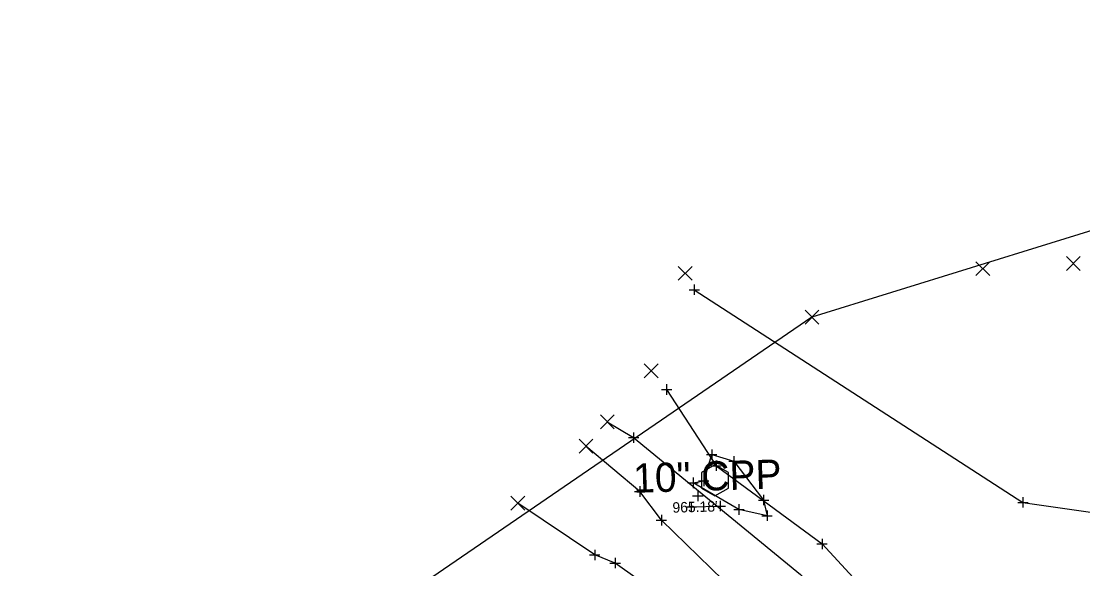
# Model space of a CAD drawing. Extents: x 120332 to 120776, y 463407 to 463745.
# Drawn here: x 120359.6 to 120461.5, y 463602.7 to 463655.3 of the extents above; entities that cross this region are included whole.
import ezdxf

# ---------------------------------------------------------------- set-up
doc = ezdxf.new("R2010")
doc.units = 0
for name, color, linetype in [('DR_X_Erosion_Control', 7, 'Continuous'), ('DR_X_Storm_Sewer', 7, 'Continuous'), ('DR_X_Text', 7, 'Continuous'), ('DV_X_Property_Line', 7, 'Continuous'), ('RD_X_RR_Cells', 7, 'Continuous'), ('SC_Scratch1', 7, 'Continuous'), ('SV_P_Control_Cells_Set', 7, 'Continuous'), ('SV_P_Mon_Cells_Set', 7, 'Continuous'), ('SV_X_Break_Lines', 7, 'Continuous'), ('SV_X_Mon_Cells_Found', 7, 'Continuous'), ('SV_X_Random_Point', 7, 'Continuous'), ('SV_X_Terrain_Boundary', 7, 'Continuous')]:
    doc.layers.add(name, color=color, linetype=linetype)

msp = doc.modelspace()

# ---------------------------------------------------------------- linework, layer by layer
at = {"layer": 'DR_X_Erosion_Control'}
msp.add_lwpolyline([(120425.12, 463611.16), (120425.88, 463613.69), (120428.02, 463613.05), (120430.86, 463609.33), (120431.19, 463607.83), (120428.5, 463608.42), (120424.09, 463610.98)], close=True, dxfattribs=at)
at = {"layer": 'DR_X_Storm_Sewer'}
msp.add_line((120423.92, 463608.67), (120426.71, 463608.75), dxfattribs=at)
at = {"layer": 'DV_X_Property_Line'}
for p, q in [((120423.92, 463609.17), (120423.92, 463608.17)), ((120426.71, 463609.25), (120426.71, 463608.25)), ((120423.42, 463608.67), (120424.42, 463608.67)), ((120423.92, 463608.67), (120423.92, 463608.67)), ((120426.21, 463608.75), (120427.21, 463608.75)), ((120426.71, 463608.75), (120426.71, 463608.75))]:
    msp.add_line(p, q, dxfattribs=at)
at = {"layer": 'RD_X_RR_Cells'}
for points in [[(120421.56, 463619.93), (120426.3, 463612.62), (120436.47, 463605.12), (120443.17, 463597.87), (120449.32, 463591.39), (120456.91, 463583.55), (120459.12, 463582.05), (120462.23, 463580.42), (120466.75, 463584.83), (120476.93, 463591.15), (120482.16, 463596.63), (120497.16, 463604.58), (120521.1, 463620.25), (120539.56, 463634.42)], [(120375.09, 463513.46), (120396.65, 463529.7), (120416.31, 463546.41), (120423.97, 463550.77), (120436.34, 463560.17), (120443.81, 463566.35), (120445.29, 463570.72), (120445.41, 463574.22), (120441.35, 463579.5), (120435.84, 463588.34), (120428.62, 463594.75), (120416.62, 463603.29), (120414.66, 463604.06), (120407.29, 463609.02)]]:
    msp.add_lwpolyline(points, dxfattribs=at)
at = {"layer": 'SC_Scratch1'}
msp.add_lwpolyline([(120424.89, 463610.47), (120426.19, 463609.72), (120427.49, 463610.47), (120427.49, 463611.97), (120426.19, 463612.72), (120424.89, 463611.97), (120424.89, 463610.47)], dxfattribs=at)
at = {"layer": 'SV_P_Control_Cells_Set'}
for p, q in [((120459.91, 463631.36), (120461.25, 463632.69)), ((120459.91, 463632.69), (120461.25, 463631.36)), ((120422.67, 463630.41), (120424, 463631.74)), ((120422.67, 463631.74), (120424, 463630.41)), ((120451.24, 463630.85), (120452.57, 463632.18)), ((120451.24, 463632.18), (120452.57, 463630.85)), ((120434.84, 463626.19), (120436.17, 463627.53)), ((120434.84, 463627.53), (120436.17, 463626.19)), ((120419.41, 463621.06), (120420.74, 463622.39)), ((120419.41, 463622.39), (120420.74, 463621.06)), ((120415.2, 463616.17), (120416.53, 463617.5)), ((120415.2, 463617.5), (120416.53, 463616.17)), ((120413.16, 463613.83), (120414.49, 463615.16)), ((120413.16, 463615.16), (120414.49, 463613.83)), ((120406.62, 463608.36), (120407.96, 463609.69)), ((120406.62, 463609.69), (120407.96, 463608.36))]:
    msp.add_line(p, q, dxfattribs=at)
at = {"layer": 'SV_P_Mon_Cells_Set'}
msp.add_lwpolyline([(120424.21, 463629.5), (120455.74, 463609.1), (120479.05, 463605.78), (120493.61, 463611.68), (120534.99, 463638.96)], dxfattribs=at)
at = {"layer": 'SV_X_Break_Lines'}
msp.add_lwpolyline([(120415.86, 463616.83), (120418.39, 463615.32), (120434.39, 463602.18), (120440.95, 463596.06), (120447.6, 463588.4), (120454.45, 463580.2), (120458.76, 463578.15)], dxfattribs=at)
at = {"layer": 'SV_X_Mon_Cells_Found'}
for p, q in [((120423.71, 463629.5), (120424.71, 463629.5)), ((120424.21, 463630), (120424.21, 463629)), ((120424.21, 463629.5), (120424.21, 463629.5)), ((120421.56, 463620.43), (120421.56, 463619.43)), ((120421.06, 463619.93), (120422.06, 463619.93)), ((120421.56, 463619.93), (120421.56, 463619.93)), ((120417.89, 463615.32), (120418.89, 463615.32)), ((120418.39, 463615.82), (120418.39, 463614.82)), ((120418.39, 463615.32), (120418.39, 463615.32)), ((120425.88, 463614.19), (120425.88, 463613.19)), ((120425.38, 463613.69), (120426.38, 463613.69)), ((120425.88, 463613.69), (120425.88, 463613.69)), ((120426.3, 463613.12), (120426.3, 463612.12)), ((120428.02, 463613.55), (120428.02, 463612.55)), ((120425.8, 463612.62), (120426.8, 463612.62)), ((120426.3, 463612.62), (120426.3, 463612.62)), ((120427.52, 463613.05), (120428.52, 463613.05)), ((120428.02, 463613.05), (120428.02, 463613.05)), ((120424.09, 463611.48), (120424.09, 463610.48)), ((120424.62, 463611.16), (120425.62, 463611.16)), ((120425.12, 463611.66), (120425.12, 463610.66)), ((120425.12, 463611.16), (120425.12, 463611.16)), ((120418.48, 463610.15), (120419.48, 463610.15)), ((120418.98, 463610.65), (120418.98, 463609.65)), ((120418.98, 463610.15), (120418.98, 463610.15)), ((120423.59, 463610.98), (120424.59, 463610.98)), ((120424.09, 463610.98), (120424.09, 463610.98)), ((120424.55, 463610.22), (120424.55, 463609.22)), ((120424.05, 463609.72), (120425.05, 463609.72)), ((120424.55, 463609.72), (120424.55, 463609.72)), ((120430.36, 463609.33), (120431.36, 463609.33)), ((120430.86, 463609.83), (120430.86, 463608.83)), ((120430.86, 463609.33), (120430.86, 463609.33)), ((120455.24, 463609.1), (120456.24, 463609.1)), ((120455.74, 463609.6), (120455.74, 463608.6)), ((120455.74, 463609.1), (120455.74, 463609.1)), ((120428, 463608.42), (120429, 463608.42)), ((120428.5, 463608.92), (120428.5, 463607.92)), ((120428.5, 463608.42), (120428.5, 463608.42)), ((120431.19, 463608.33), (120431.19, 463607.33)), ((120420.56, 463607.4), (120421.56, 463607.4)), ((120421.06, 463607.9), (120421.06, 463606.9)), ((120421.06, 463607.4), (120421.06, 463607.4)), ((120430.69, 463607.83), (120431.69, 463607.83)), ((120431.19, 463607.83), (120431.19, 463607.83)), ((120435.97, 463605.12), (120436.97, 463605.12)), ((120436.47, 463605.62), (120436.47, 463604.62)), ((120436.47, 463605.12), (120436.47, 463605.12)), ((120414.16, 463604.06), (120415.16, 463604.06)), ((120414.66, 463604.56), (120414.66, 463603.56)), ((120414.66, 463604.06), (120414.66, 463604.06)), ((120416.12, 463603.29), (120417.12, 463603.29)), ((120416.62, 463603.79), (120416.62, 463602.79)), ((120416.62, 463603.29), (120416.62, 463603.29))]:
    msp.add_line(p, q, dxfattribs=at)
at = {"layer": 'SV_X_Random_Point'}
msp.add_lwpolyline([(120456.47, 463572.24), (120451.19, 463577.05), (120445.9, 463580.97), (120439.87, 463588.76), (120431.73, 463597.04), (120421.06, 463607.4), (120418.98, 463610.15), (120413.82, 463614.49)], dxfattribs=at)
at = {"layer": 'SV_X_Terrain_Boundary'}
msp.add_lwpolyline([(120382.05, 463504.31), (120392.05, 463491.7), (120404.48, 463476.09), (120419.01, 463449.44), (120492.05, 463471.81), (120514.57, 463481.5), (120536.71, 463497.24), (120541.46, 463506.92), (120568.63, 463561.6), (120583.37, 463575.39), (120540.78, 463632.41), (120527.21, 463655.25), (120435.5, 463626.86), (120399.02, 463601.89), (120359.63, 463534.8), (120382.05, 463504.31)], dxfattribs=at)

# ---------------------------------------------------------------- texts
at = {"layer": 'DR_X_Text'}
msp.add_text('10" CPP', height=2.8, rotation=1.6906, dxfattribs=at).set_placement((120418.39, 463610.02))
at = {"layer": 'SC_Scratch1'}
msp.add_text("965.18'", height=1, rotation=1.6906, dxfattribs=at).set_placement((120422.13, 463608.11))

doc.saveas('drawing.dxf')
